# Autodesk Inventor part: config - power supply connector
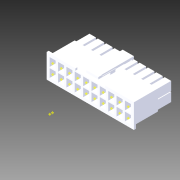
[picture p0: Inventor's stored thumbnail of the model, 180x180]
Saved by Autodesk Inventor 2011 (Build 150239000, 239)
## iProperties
Company: Autodesk Inc.
Created: 2005-12
Part Number: config - power supply connector
Document SubType Name: Modeling
Designer: Autodesk Inc.
Stock Number: config - power supply connector
Density: 1 g/cm^3
Categories: <MemberInstance><Categories><Category DisplayName="" Mnemonic="CABLEANDHARNESS" InternalName="e4a7e005-5e42-4d16-b293-125e7f0d0512"><Category DisplayName="" Mne
Mass: 3.42543 g
Surface Area: 97.1667 cm^2
Volume: 3.42543 cm^3
Title: PC Demo
Author: Autodesk Inc.
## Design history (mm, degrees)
sketch "Sketch1"
  geometry: L1 (0, 8.4)-(0, -8.4) reference; L2 (-38.183, 0)-(31.817, 0) reference; L3 (-20.817, 5)-(20.817, 5); L4 (20.817, 5)-(20.817, -5); L5 (20.817, -5)-(-20.817, -5); L6 (-20.817, -5)-(-20.817, 5)
  constraints: 8 end point, 2 parallel, 1 horizontal, 1 perpendicular, 2 other
  dimensions: "d0" = 41.634 distance of L3.start L3.end; "d1" = 10 distance of L5.end L3.start
extrude "Extrusion1" new body sketch "Sketch1" distance "d2" = 10; taper "d3" = 0 deg
workplane "Work Plane1"
sketch "Sketch2"
  geometry: L1 (20.817, 5)-(20.817, -5) reference; L2 (-20.817, 5)-(20.817, 5) reference; L3 (-20.817, -5)-(-20.817, 5) reference; L4 (20.817, -5)-(-20.817, -5) reference
extrude "Extrusion2" join sketch "Sketch2" distance "d5" = 13; taper "d6" = 0 deg
sketch "Sketch3"
  geometry: L1 (20.817, -5)-(-20.817, -5) reference; L2 (20.817, 5)-(20.817, -5) reference; L3 (-20.817, 5)-(20.817, 5) reference; L4 (-20.817, -5)-(-20.817, 5) reference; L5 (21.817, 6)-(21.817, -6); L6 (21.817, -6)-(-21.817, -6); L7 (-21.817, -6)-(-21.817, 6); L8 (-21.817, 6)-(21.817, 6)
  constraints: 8 end point, 3 other
  dimensions: "d7" = 1 distance between parallel lines of L8 L3
extrude "Extrusion3" join sketch "Sketch3" distance "d8" = 1; taper "d9" = 0 deg
sketch "Sketch4"
  geometry: L1 (-20.817, 5)-(20.817, 5) reference; L2 (-20.817, -5)-(-20.817, 5) reference; L3 (20.817, -5)-(-20.817, -5) reference; L4 (20.817, 5)-(20.817, -5) reference; L5 (20.317, 4.5)-(17.317, 4.5); L6 (17.317, 4.5)-(17.317, 0.3); L7 (17.317, 0.3)-(20.317, 0.3); L8 (20.317, 0.3)-(20.317, 4.5); L9 (20.317, -0.3)-(17.317, -0.3); L10 (17.317, -0.3)-(17.317, -4.5); L11 (17.317, -4.5)-(20.317, -4.5); L12 (20.317, -4.5)-(20.317, -0.3)
  constraints: 16 end point, 4 parallel, 3 collinear, 2 horizontal, 2 perpendicular
  dimensions: "d10" = 0.5 distance between parallel lines of L1 L5; "d11" = 0.5 distance between parallel lines of L3 L11 (= d10); "d12" = 4.2 distance of L5.end L6.end; "d13" = 0.5 distance between parallel lines of L4 L8; "d14" = 3 distance of L5.start L5.end
extrude "Extrusion4" cut sketch "Sketch4" distance "d15" = 16; taper "d16" = 0 deg
pattern_linear "Rectangular Pattern1" dims "d19" = 4.182
split "Split1"
sketch "Sketch8"
  geometry: L1 (21.817, -6)-(-21.817, -6) reference; L2 (0, 8.4)-(0, -8.4) reference; L3 (-7.5, -6)-(7.5, -6); L4 (7.5, -6)-(7.5, -5); L5 (7.5, -5)-(-7.5, -5); L6 (-7.5, -5)-(-7.5, -6)
  constraints: 8 end point, 2 parallel, 1 horizontal, 1 perpendicular, 1 point on line, 1 other
  dimensions: "d36" = 15 distance of L4.end L5.end; "d37" = 1 distance of L5.end L3.start
extrude "Extrusion8" cut sketch "Sketch8" stored distance "d38" = 6; taper "d39" = 0 deg
sketch "Sketch5"
  geometry: L1 (41.634, 10)-(0, 10) reference; L2 (20.817, 51.984)-(20.817, -8.664) reference; L3 (18.817, 8)-(22.817, 8); L4 (22.817, 8)-(22.817, 5); L5 (22.817, 5)-(18.817, 5); L6 (18.817, 5)-(18.817, 8)
  constraints: 8 end point, 2 parallel, 1 horizontal, 1 perpendicular, 1 other
  dimensions: "d20" = 4 distance of L4.end L5.end; "d21" = 3 distance of L3.end L4.end; "d22" = 2 distance between parallel lines of L1 L3
extrude "Extrusion5" join sketch "Sketch5" distance "d23" = 1; taper "d24" = 0 deg
sketch "Sketch6"
  geometry: L1 (-5, 10)-(-5, 22) reference; L2 (-5, 5)-(-6, 5) reference; L3 (-6, 8)-(-6, 5) reference; L4 (-6, 4)-(-7, 4); L5 (-7, 4)-(-7, 22); L6 (-7, 22)-(-6, 22); L7 (-6, 22)-(-6, 4); L8 (-6, 5)-(-5.3, 5); L9 (-6, 4)-(-5.3, 5); L10 (-5.3, 5)-(-6, 5); L11 (-5.3, 5)-(-6, 5); L12 (-6, 4)-(-6, 5); 1 further point
  constraints: 18 end point, 4 equal length, 2 perpendicular, 1 collinear, 1 horizontal, 1 point on line
  dimensions: "d25" = 1 distance of L4.start L4.end; "d26" = 1 distance between parallel lines of L4 L2; "d27" = 18 distance of L4.end L5.end; "d28" = 35 deg angle of L7 L9
extrude "Extrusion6" join sketch "Sketch6" stored distance "d29" = 6; taper "d30" = 0 deg
sketch "Sketch7"
  geometry: L1 (6, -18)-(6, 0) reference; L2 (0, 0)-(6, 0) reference; L3 (0, 0)-(0, -18) reference; L4 (0, -6)-(1, -6); L5 (1, -6)-(1, -8.5); L6 (1, -8.5)-(0, -8.5); L7 (0, -8.5)-(0, -6); L8 (6, -6)-(5, -6); L9 (5, -6)-(5, -8.5); L10 (5, -8.5)-(6, -8.5); L11 (6, -8.5)-(6, -6)
  constraints: 16 end point, 4 parallel, 3 collinear, 2 horizontal, 2 perpendicular, 2 point on line
  dimensions: "d31" = 6 distance between parallel lines of L4 L2; "d32" = 2.5 distance of L4.end L5.end; "d33" = 1 distance of L5.end L6.end
extrude "Extrusion7" join sketch "Sketch7" stored distance "d34" = 6; taper "d35" = 0 deg
sketch "Sketch9"
  geometry: L1 (-4, -7)-(-22, -7) reference; L2 (-4, -6)-(-4, -7) reference; L3 (-5, -5.3)-(-4, -6) reference; L4 (-5, -6)-(-5, -5.3) reference; L5 (-13.5, -6)-(-5, -6) reference; L6 (-20.169, -7)-(-20.169, -6.371); L7 (-20.169, -6.371)-(-13.107, -6.371); L8 (-13.107, -6)-(-13.107, -6.371)
  constraints: 6 end point, 2 perpendicular, 2 point on line, 1 parallel
extrude "Extrusion9" cut sketch "Sketch9" distance "d40" = 0.2; taper "d41" = 0 deg
mirror "Mirror1"
sketch "Sketch11"
  geometry: L1 (20.817, 5)-(-20.817, 5) reference; L2 (-20.817, 5)-(-20.817, -5) reference; L3 (-20.817, -5)-(20.817, -5) reference; L4 (20.817, -5)-(20.817, 5) reference; L5 (4.775, -4.5)-(7.775, -4.5) reference; L6 (3.593, 0.3)-(3.593, 4.5) reference; L7 (3.593, 4.5)-(0.593, 4.5) reference; L8 (0.593, 4.5)-(0.593, 0.3) reference; L9 (0.593, 0.3)-(3.593, 0.3) reference; L10 (3.593, -4.5)-(3.593, -0.3) reference; L11 (3.593, -0.3)-(0.593, -0.3) reference; L12 (0.593, -0.3)-(0.593, -4.5) reference; L13 (0.593, -4.5)-(3.593, -4.5) reference; L14 (-0.589, 0.3)-(-0.589, 4.5) reference; L15 (-0.589, 4.5)-(-3.589, 4.5) reference; L16 (-3.589, 4.5)-(-3.589, 0.3) reference; L17 (-3.589, 0.3)-(-0.589, 0.3) reference; L18 (-0.589, -4.5)-(-0.589, -0.3) reference; L19 (-0.589, -0.3)-(-3.589, -0.3) reference; L20 (-3.589, -0.3)-(-3.589, -4.5) reference; L21 (-3.589, -4.5)-(-0.589, -4.5) reference; L22 (-4.771, 0.3)-(-4.771, 4.5) reference; L23 (-4.771, 4.5)-(-7.771, 4.5) reference; L24 (-7.771, 4.5)-(-7.771, 0.3) reference; L25 (-7.771, 0.3)-(-4.771, 0.3) reference; L26 (-4.771, -4.5)-(-4.771, -0.3) reference; L27 (-4.771, -0.3)-(-7.771, -0.3) reference; L28 (-7.771, -0.3)-(-7.771, -4.5) reference; L29 (-7.771, -4.5)-(-4.771, -4.5) reference; L30 (-8.953, 0.3)-(-8.953, 4.5) reference; L31 (-8.953, 4.5)-(-11.953, 4.5) reference; L32 (-11.953, 4.5)-(-11.953, 0.3) reference; L33 (-11.953, 0.3)-(-8.953, 0.3) reference; L34 (-8.953, -4.5)-(-8.953, -0.3) reference; L35 (-8.953, -0.3)-(-11.953, -0.3) reference; L36 (-11.953, -0.3)-(-11.953, -4.5) reference; L37 (-11.953, -4.5)-(-8.953, -4.5) reference; L38 (-13.135, 0.3)-(-13.135, 4.5) reference; L39 (-13.135, 4.5)-(-16.135, 4.5) reference; L40 (-16.135, 4.5)-(-16.135, 0.3) reference; L41 (-16.135, 0.3)-(-13.135, 0.3) reference; L42 (-13.135, -4.5)-(-13.135, -0.3) reference; L43 (-13.135, -0.3)-(-16.135, -0.3) reference; L44 (-16.135, -0.3)-(-16.135, -4.5) reference; L45 (-16.135, -4.5)-(-13.135, -4.5) reference; L46 (-17.317, 0.3)-(-17.317, 4.5) reference; L47 (-17.317, 4.5)-(-20.317, 4.5) reference; L48 (-20.317, 4.5)-(-20.317, 0.3) reference; L49 (-20.317, 0.3)-(-17.317, 0.3) reference; L50 (-17.317, -4.5)-(-17.317, -0.3) reference; L51 (-17.317, -0.3)-(-20.317, -0.3) reference; L52 (-20.317, -0.3)-(-20.317, -4.5) reference; L53 (-20.317, -4.5)-(-17.317, -4.5) reference; L54 (-7.5, -5)-(-7.5, -6) reference; L55 (-21.817, -6)-(-7.5, -6) reference; L56 (-21.817, 6)-(-21.817, -6) reference; L57 (21.817, 6)-(-21.817, 6) reference; L58 (21.817, -6)-(21.817, 6) reference; L59 (7.5, -6)-(21.817, -6) reference; L60 (7.5, -6)-(7.5, -5) reference; L61 (7.5, -5)-(-7.5, -5) reference; L62 (20.321, 0.3)-(20.321, 4.5) reference; L63 (20.321, 4.5)-(17.321, 4.5) reference; L64 (17.321, 4.5)-(17.321, 0.3) reference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
extrude "Extrusion11" cut sketch "Sketch11" distance "d49" = 10; taper "d50" = 0 deg
sketch "Sketch12"
  geometry: L1 (-17.217, -4.6)-(-20.417, -4.6); L2 (-20.417, -4.6)-(-20.417, -0.2); L3 (-20.417, -0.2)-(-17.217, -0.2); L4 (-17.217, -0.2)-(-17.217, -4.6); L5 (-17.817, -4)-(-19.817, -4); L6 (-19.817, -4)-(-19.817, -0.8); L7 (-19.817, -0.8)-(-17.817, -0.8); L8 (-17.817, -0.8)-(-17.817, -4)
  constraints: 16 end point, 4 parallel, 2 horizontal, 2 perpendicular
extrude "Extrusion12" join sketch "Sketch12" distance "d59" = 7; taper "d60" = 0 deg
workplane "Work Plane2"
workplane "Work Plane3"
sketch "Sketch13"
  geometry: L1 (7.5, -5)-(7.5, -6) reference; L2 (21.817, -6)-(7.5, -6) reference; L3 (21.817, 6)-(21.817, -6) reference; L4 (-21.817, 6)-(21.817, 6) reference; L5 (-21.817, -6)-(-21.817, 6) reference; L6 (-7.5, -6)-(-21.817, -6) reference; L7 (-7.5, -6)-(-7.5, -5) reference; L8 (-7.5, -5)-(7.5, -5) reference; L9 (-24.5, 0.3)-(-24.5, 4.5) reference; L10 (-24.5, 4.5)-(-21.5, 4.5) reference; L11 (-21.5, 4.5)-(-21.5, 0.3) reference; L12 (-21.5, 0.3)-(-24.5, 0.3) reference; L13 (-24.5, -4.5)-(-24.5, -0.3) reference; L14 (-24.5, -0.3)-(-21.5, -0.3) reference; L15 (-21.5, -0.3)-(-21.5, -4.5) reference; L16 (-21.5, -4.5)-(-24.5, -4.5) reference; L17 (-20.318, 0.3)-(-20.318, 4.5) reference; L18 (-20.318, 4.5)-(-21.501, 4.5) reference; L19 (-21.501, 4.5)-(-21.501, 0.3) reference; L20 (-21.501, 0.3)-(-20.318, 0.3) reference; L21 (-20.318, -4.5)-(-20.318, -0.3) reference; L22 (-20.318, -0.3)-(-21.501, -0.3) reference; L23 (-21.501, -0.3)-(-21.501, -4.5) reference; L24 (-21.501, -4.5)-(-20.318, -4.5) reference; L25 (-20.321, 0.3)-(-20.321, 4.5) reference; L26 (-20.321, 4.5)-(-17.321, 4.5) reference; L27 (-17.321, 4.5)-(-17.321, 0.3) reference; L28 (-17.321, 0.3)-(-20.321, 0.3) reference; L29 (-20.321, -4.5)-(-20.321, -0.3) reference; L30 (-20.321, -0.3)-(-17.321, -0.3) reference; L31 (-17.321, -0.3)-(-17.321, -4.5) reference; L32 (-17.321, -4.5)-(-20.321, -4.5) reference; L33 (-16.139, 0.3)-(-16.139, 4.5) reference; L34 (-16.139, 4.5)-(-13.139, 4.5) reference; L35 (-13.139, 4.5)-(-13.139, 0.3) reference; L36 (-13.139, 0.3)-(-16.139, 0.3) reference; L37 (-16.139, -4.5)-(-16.139, -0.3) reference; L38 (-16.139, -0.3)-(-13.139, -0.3) reference; L39 (-13.139, -0.3)-(-13.139, -4.5) reference; L40 (-13.139, -4.5)-(-16.139, -4.5) reference; L41 (-11.957, 0.3)-(-11.957, 4.5) reference; L42 (-11.957, 4.5)-(-8.957, 4.5) reference; L43 (-8.957, 4.5)-(-8.957, 0.3) reference; L44 (-8.957, 0.3)-(-11.957, 0.3) reference; L45 (-11.957, -4.5)-(-11.957, -0.3) reference; L46 (-11.957, -0.3)-(-8.957, -0.3) reference; L47 (-8.957, -0.3)-(-8.957, -4.5) reference; L48 (-8.957, -4.5)-(-11.957, -4.5) reference; L49 (-7.775, 0.3)-(-7.775, 4.5) reference; L50 (-7.775, 4.5)-(-4.775, 4.5) reference; L51 (-4.775, 4.5)-(-4.775, 0.3) reference; L52 (-4.775, 0.3)-(-7.775, 0.3) reference; L53 (-7.775, -4.5)-(-7.775, -0.3) reference; L54 (-7.775, -0.3)-(-4.775, -0.3) reference; L55 (-4.775, -0.3)-(-4.775, -4.5) reference; L56 (-4.775, -4.5)-(-7.775, -4.5) reference; L57 (-3.593, 0.3)-(-3.593, 4.5) reference; L58 (-3.593, 4.5)-(-0.593, 4.5) reference; L59 (-0.593, 4.5)-(-0.593, 0.3) reference; L60 (-0.593, 0.3)-(-3.593, 0.3) reference; L61 (-3.593, -4.5)-(-3.593, -0.3) reference; L62 (-3.593, -0.3)-(-0.593, -0.3) reference; L63 (-0.593, -0.3)-(-0.593, -4.5) reference; L64 (-0.593, -4.5)-(-3.593, -4.5) reference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; C1 r 1 at (-27.183, 2.4) reference; C2 r 1 at (-27.183, -2.4) reference; C3 r 1 at (-23.001, 2.4) reference; C4 r 1 at (-23.001, -2.4) reference; C5 r 1 at (-18.819, 2.4) reference; C6 r 1 at (-18.819, -2.4) reference; C7 r 1 at (-14.638, 2.4) reference; C8 r 1 at (-14.638, -2.4) reference; C9 r 1 at (-10.456, 2.4) reference; C10 r 1 at (-10.456, -2.4) reference; C11 r 1 at (-6.274, 2.4) reference; C12 r 1 at (-6.274, -2.4) reference; C13 r 1 at (-2.092, 2.4) reference; C14 r 1 at (-2.092, -2.4) reference; C15 r 1 at (2.09, 2.4) reference; C16 r 1 at (2.09, -2.4) reference; C17 r 1 at (6.272, 2.4) reference; C18 r 1 at (6.272, -2.4) reference; C19 r 1 at (10.453, 2.4) reference; C20 r 1 at (10.453, -2.4) reference; C21 r 1 at (14.635, 2.4) reference; C22 r 1 at (14.635, -2.4) reference; C23 r 1 at (18.817, 2.4) reference; C24 r 1 at (18.817, -2.4) reference
node "1"
node "2"
node "3"
node "4"
node "5"
node "6"
node "7"
node "8"
node "9"
node "10"
node "11"
node "12"
node "13"
node "14"
node "15"
node "16"
node "17"
node "18"
node "19"
node "20"
sketch "Sketch14"
  geometry: L1 (-20.321, 4.5)-(-17.321, 4.5) reference; L2 (20.317, -4.5)-(17.317, -4.5) reference; L3 (-20.321, 4.5)-(20.317, -4.5); 1 further point
  constraints: 2 end point, 1 midpoint
workpoint "Work Point25"
sketch "Sketch15"
  geometry: 1 further point
workpoint "Work Point26"
body "Solid1"
pattern_linear "Rectangular Pattern3" dims "d63" = 4.182, "d66" = 4.8
node "Projected Loop2"
other parameters: "d4" = 0, "d51" = 0.1, "d52" = 0.1, "d53" = 0.1, "d54" = 0.1, "d55" = 0.5, "d56" = 0.5, "d57" = 0.5, "d58" = 0.5, "d67" = 19.05, "d68" = 20.32
